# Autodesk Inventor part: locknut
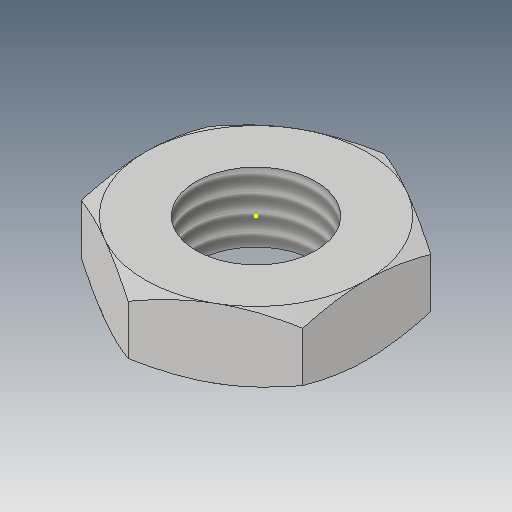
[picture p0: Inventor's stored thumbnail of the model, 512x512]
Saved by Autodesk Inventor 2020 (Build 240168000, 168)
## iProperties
Created: 2016-05
Part Number: locknut
Material: Generic
Document SubType Name: Modeling
Designer: CADCIM
Density: 1 g/cm^3
Appearance: Default
Author: CADCIM
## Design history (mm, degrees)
sketch "Sketch1"
  geometry: L1 (9.6, -5.543)-(0, -11.085); L2 (0, -11.085)-(-9.6, -5.543); L3 (-9.6, -5.543)-(-9.6, 5.543); L4 (-9.6, 5.543)-(0, 11.085); L5 (0, 11.085)-(9.6, 5.543); L6 (9.6, 5.543)-(9.6, -5.543); 2 further points
  constraints: 12 end point, 1 coincident, 1 vertical alignment, 13 other
  dimensions: "d0" = 19.2 distance between parallel lines of L3 L6
extrude "Extrusion1" new body sketch "Sketch1" distance "d1" = 6; taper "d2" = 0 deg
sketch "Sketch2"
  geometry: L1 (0, 11.085)-(-9.6, 5.543) reference; C1 r 9.6 at (0, 0); 1 further point
  constraints: 1 centre point, 1 coincident, 1 tangent
extrude "Extrusion2" sketch "Sketch2" distance "d3" = 10.8; taper "d4" = 60 deg
workplane "Work Plane1"
sketch "Sketch3"
  geometry: L1 (0, -11.085)-(9.6, -5.543) reference; C1 r 9.6 at (0, 0); 1 further point
  constraints: 1 centre point, 1 coincident, 1 tangent
extrude "Extrusion3" sketch "Sketch3" distance "d5" = 10.8; taper "d6" = 60 deg
sketch "Sketch4"
  geometry: 1 further point
hole "Hole1" diameter "d9" = 10.376; stored, may be unused: countersink angle "d13" = 90 deg, drill point angle "d15" = 118 deg; dims "d7" = 10, "d8" = 10, "d10" = 24, "d11" = 4, "d12" = 2, "d14" = 31.3
body "Solid1"
